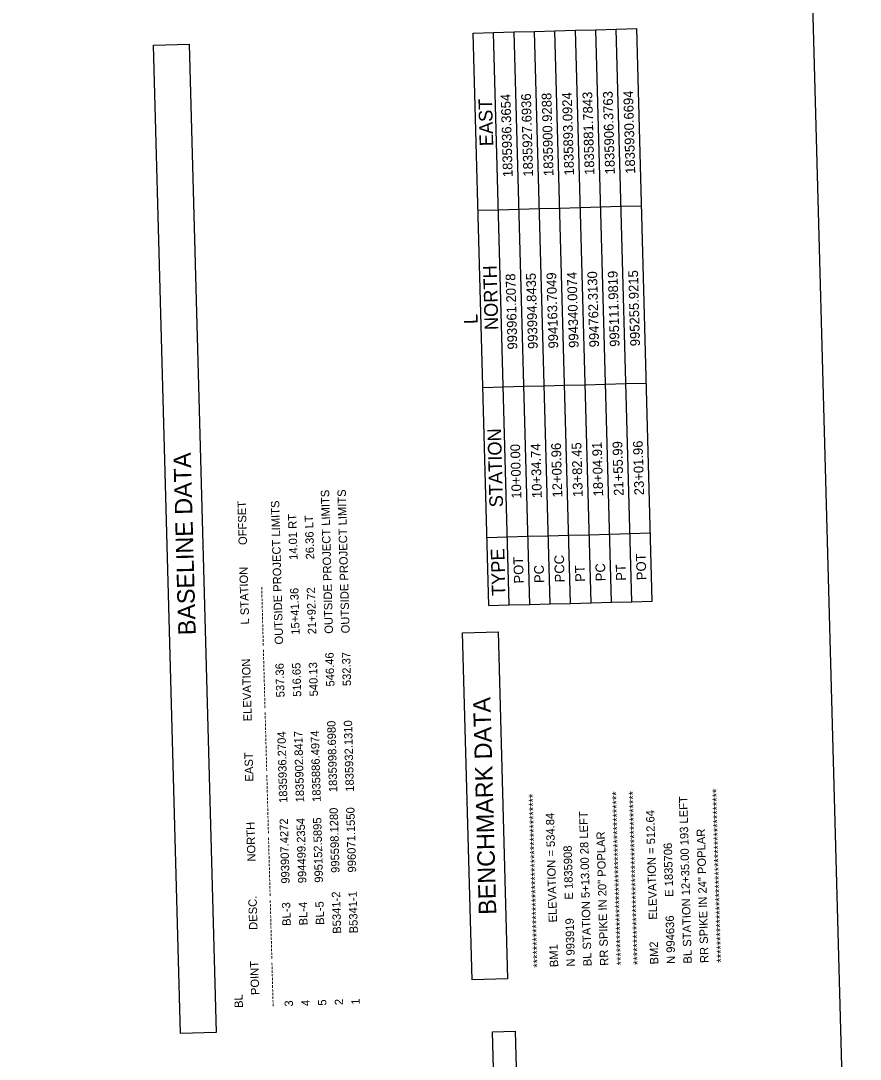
# Model space of a CAD drawing. Extents: x 1835096 to 1837089, y 993071 to 995976.
# Drawn here: x 1836175 to 1837037, y 994065 to 995131 of the extents above; entities that cross this region are included whole.
import ezdxf

# ---------------------------------------------------------------- set-up
doc = ezdxf.new("R2010")
doc.units = 0
for name, color, linetype in [('CTL Sheet Border CELL', 7, 'Continuous'), ('CTL Sheet Notes CELL', 7, 'Continuous'), ('CTL Sheet Table Cell', 7, 'Continuous'), ('CTL Sheet Text', 7, 'Continuous')]:
    doc.layers.add(name, color=color, linetype=linetype)

msp = doc.modelspace()

# ---------------------------------------------------------------- linework, layer by layer
at = {"layer": 'CTL Sheet Border CELL'}
for points in [[(1835140.8, 995926.5), (1835212, 993318.7), (1837037.4, 993368.6), (1836966.2, 995976.3)], [(1836339.3, 994091.5), (1836311.6, 995106.3), (1836348, 995107.3), (1836375.7, 994092.6)], [(1836638.7, 994146.8), (1836629, 994503.1), (1836665.4, 994504.1), (1836675.1, 994147.8)], [(1836677.8, 993428.1), (1836659.6, 994093.4), (1836682.9, 994094), (1836701.1, 993428.8)]]:
    msp.add_lwpolyline(points, close=True, dxfattribs=at)
at = {"layer": 'CTL Sheet Table Cell'}
for p, q in [((1836702.8, 995120.5), (1836723.8, 995121.1)), ((1836723.8, 995121.1), (1836744.8, 995121.6)), ((1836739.9, 994533.3), (1836723.8, 995121.1)), ((1836744.8, 995121.6), (1836765.8, 995122.2)), ((1836760.9, 994533.9), (1836744.8, 995121.6)), ((1836765.8, 995122.2), (1836786.8, 995122.8)), ((1836781.8, 994534.4), (1836765.8, 995122.2)), ((1836786.8, 995122.8), (1836807.8, 995123.4)), ((1836802.8, 994535), (1836786.8, 995122.8)), ((1836823.8, 994535.6), (1836807.8, 995123.4)), ((1836639.8, 995118.8), (1836660.8, 995119.4)), ((1836655.9, 994531), (1836639.8, 995118.8)), ((1836660.8, 995119.4), (1836681.8, 995119.9)), ((1836676.9, 994531.6), (1836660.8, 995119.4)), ((1836681.8, 995119.9), (1836702.8, 995120.5)), ((1836697.9, 994532.1), (1836681.8, 995119.9)), ((1836718.9, 994532.7), (1836702.8, 995120.5)), ((1836749.8, 994939.7), (1836770.8, 994940.3)), ((1836770.8, 994940.3), (1836791.8, 994940.9)), ((1836791.8, 994940.9), (1836812.7, 994941.4)), ((1836644.8, 994936.8), (1836665.8, 994937.4)), ((1836665.8, 994937.4), (1836686.8, 994938)), ((1836686.8, 994938), (1836707.8, 994938.6)), ((1836707.8, 994938.6), (1836728.8, 994939.1)), ((1836728.8, 994939.1), (1836749.8, 994939.7)), ((1836775.7, 994758.4), (1836796.7, 994758.9)), ((1836796.7, 994758.9), (1836817.7, 994759.5)), ((1836649.8, 994754.9), (1836670.8, 994755.5)), ((1836670.8, 994755.5), (1836691.8, 994756.1)), ((1836691.8, 994756.1), (1836712.8, 994756.6)), ((1836712.8, 994756.6), (1836733.7, 994757.2)), ((1836733.7, 994757.2), (1836754.7, 994757.8)), ((1836754.7, 994757.8), (1836775.7, 994758.4)), ((1836654, 994601), (1836675, 994601.5)), ((1836675, 994601.5), (1836696, 994602.1)), ((1836696, 994602.1), (1836717, 994602.7)), ((1836717, 994602.7), (1836738, 994603.3)), ((1836738, 994603.3), (1836758.9, 994603.8)), ((1836758.9, 994603.8), (1836779.9, 994604.4)), ((1836779.9, 994604.4), (1836800.9, 994605)), ((1836800.9, 994605), (1836821.9, 994605.6)), ((1836781.8, 994534.4), (1836802.8, 994535)), ((1836802.8, 994535), (1836823.8, 994535.6)), ((1836655.9, 994531), (1836676.9, 994531.6)), ((1836676.9, 994531.6), (1836697.9, 994532.1)), ((1836697.9, 994532.1), (1836718.9, 994532.7)), ((1836718.9, 994532.7), (1836739.9, 994533.3)), ((1836739.9, 994533.3), (1836760.9, 994533.9)), ((1836760.9, 994533.9), (1836781.8, 994534.4))]:
    msp.add_line(p, q, dxfattribs=at)

# ---------------------------------------------------------------- texts
at = {"layer": 'CTL Sheet Notes CELL'}
for s, p in [('EAST', (1836660.5, 995002.8)), ('NORTH', (1836665.7, 994814)), ('L', (1836644.5, 994820.2)), ('STATION', (1836670.6, 994632.1)), ('TYPE', (1836673.1, 994541))]:
    msp.add_text(s, height=14, rotation=91.5643, dxfattribs=at).set_placement(p)
at = {"layer": 'CTL Sheet Text'}
for s, height, p in [('1835893.0924', 10, (1836743.4, 994972.7)), ('1835881.7843', 10, (1836764.4, 994973.2)), ('1835906.3763', 10, (1836785.4, 994973.8)), ('1835930.6694', 10, (1836806.3, 994974.4)), ('1835936.3654', 10, (1836680.4, 994971)), ('1835927.6936', 10, (1836701.4, 994971.5)), ('1835900.9288', 10, (1836722.4, 994972.1)), ('993961.2078', 10, (1836685.2, 994794)), ('993994.8435', 10, (1836706.2, 994794.6)), ('994163.7049', 10, (1836727.2, 994795.1)), ('994340.0074', 10, (1836748.2, 994795.7)), ('994762.3130', 10, (1836769.2, 994796.3)), ('995111.9819', 10, (1836790.2, 994796.8)), ('995255.9215', 10, (1836811.2, 994797.4)), ('10+00.00', 10, (1836689.4, 994640.9)), ('10+34.74', 10, (1836710.4, 994641.5)), ('12+05.96', 10, (1836731.4, 994642.1)), ('13+82.45', 10, (1836752.4, 994642.6)), ('18+04.91', 10, (1836773.4, 994643.2)), ('21+55.99', 10, (1836794.4, 994643.8)), ('23+01.96', 10, (1836815.4, 994644.4)), ('BASELINE DATA', 17.906, (1836354.9, 994500.8)), ('2                     B5341-2      995598.1280     1835998.6980           546.46      OUTSIDE PROJECT LIMITS                 ', 8.58, (1836506.3, 994120.9)), ('1                     B5341-1      996071.1550     1835932.1310           532.37      OUTSIDE PROJECT LIMITS                 ', 8.58, (1836523.4, 994121.3)), ('    POINT          DESC.           NORTH             EAST          ELEVATION           L STATION       OFFSET', 8.58, (1836420.5, 994118.5)), ('3                        BL-3      993907.4272     1835936.2704           537.36      OUTSIDE PROJECT LIMITS                 ', 8.58, (1836454.8, 994119.4)), ('4                        BL-4      994499.2354     1835902.8417           516.65         15+41.36         14.01 RT', 8.58, (1836472, 994119.9)), ('5                        BL-5      995152.5895     1835886.4974           540.13         21+92.72         26.36 LT', 8.58, (1836489.1, 994120.4)), ('POT', 10, (1836691.8, 994553.8)), ('PCC', 10, (1836733.8, 994554.9)), ('POT', 10, (1836817.7, 994557.2)), ('PC ', 10, (1836712.8, 994554.3)), ('PT ', 10, (1836754.8, 994555.5)), ('PC ', 10, (1836775.8, 994556.1)), ('PT ', 10, (1836796.7, 994556.6)), ('------------ ---------------- ---------------- ---------------- ---------------- ---------------- ----------------', 8.58, (1836437.7, 994119)), ('BENCHMARK DATA', 17.906, (1836663.6, 994213.8)), ('****************************************', 8.58, (1836898.7, 994164.6)), ('****************************************', 8.58, (1836710.1, 994159.4)), ('****************************************', 8.58, (1836795.8, 994161.8)), ('****************************************', 8.58, (1836813, 994162.2)), ('BL STATION 12+35.00 193 LEFT', 8.58, (1836864.4, 994163.6)), ('BM1       ELEVATION = 534.84', 8.58, (1836727.2, 994159.9)), ('BL STATION 5+13.00 28 LEFT', 8.58, (1836761.5, 994160.8)), ('BM2       ELEVATION = 512.64', 8.58, (1836830.1, 994162.7)), ('RR SPIKE IN 24" POPLAR', 8.58, (1836881.6, 994164.1)), ('RR SPIKE IN 20" POPLAR', 8.58, (1836778.7, 994161.3)), ('N 993919      E 1835908', 8.58, (1836744.4, 994160.4)), ('N 994636      E 1835706', 8.58, (1836847.3, 994163.2)), ('BL', 8.58, (1836403.4, 994118))]:
    msp.add_text(s, height=height, rotation=91.5643, dxfattribs=at).set_placement(p)

doc.saveas('drawing.dxf')
